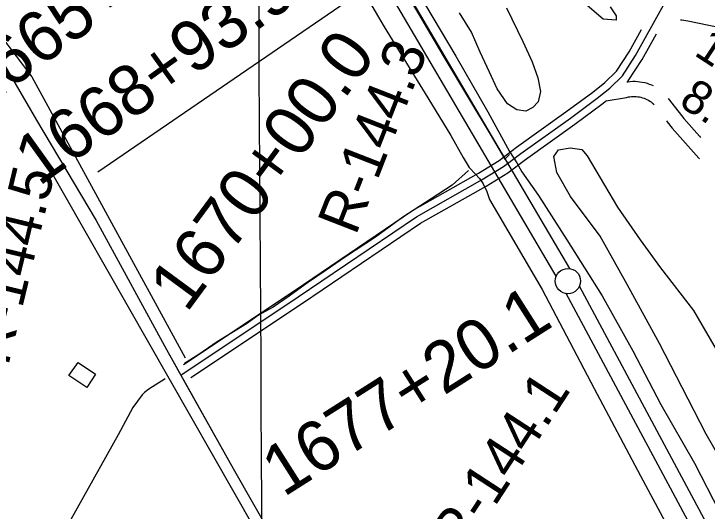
# Model space of a CAD drawing. Extents: x 3477039 to 3515015, y 546746 to 572297.
# Drawn here: x 3496548 to 3497919, y 561275 to 562259 of the extents above; entities that cross this region are included whole.
import ezdxf

# ---------------------------------------------------------------- set-up
doc = ezdxf.new("R2010")
doc.units = 0
for name, color, linetype in [('V-BLDG-OTLN', 7, 'Continuous'), ('V-FLOD-BASE', 7, 'Continuous'), ('V-GRID-MAJR', 7, 'Continuous'), ('V-LEVE-TOET', 7, 'Continuous'), ('V-RIVR-RANG', 7, 'Continuous'), ('V-RIVR-RANG-IDEN', 7, 'Continuous'), ('V-ROAD-CNTR', 7, 'Continuous'), ('V-SITE-VEGE', 7, 'Continuous'), ('V-SURV-IDEN', 7, 'Continuous'), ('V-SURV-LINE', 7, 'Continuous'), ('V-TOPO-MINR', 7, 'Continuous'), ('V-TOPO-SHOR', 7, 'Continuous')]:
    doc.layers.add(name, color=color, linetype=linetype)

msp = doc.modelspace()

# ---------------------------------------------------------------- linework, layer by layer
at = {"layer": 'V-BLDG-OTLN'}
msp.add_lwpolyline([(3496674.8850000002, 561568.976), (3496709.6350000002, 561545.756), (3496692.19, 561519.65), (3496656.9220000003, 561543.214)], close=True, dxfattribs=at)
at = {"layer": 'V-FLOD-BASE'}
msp.add_lwpolyline([(3496072.208, 562978.024), (3496198.731, 562942.932), (3496343.41, 562904.79), (3496508.679, 562860.148), (3496656.299, 562821.006), (3496768.595, 562788.941), (3496803.407, 562777.941), (3496844.078, 562761.012), (3496913.6240000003, 562725.748), (3496965.506, 562693.531), (3496995.821, 562668.801), (3497043.197, 562621.384), (3497108.16, 562557.169), (3497182.41, 562484.549), (3497238.077, 562426.77), (3497262.943, 562394.213), (3497296.559, 562345.399), (3497348.136, 562259.156), (3497396.784, 562175.876), (3497451.286, 562085.197), (3497489.725, 562020.638), (3497518.917, 561971.357), (3497528.301, 561980.636)], dxfattribs=at)
at = {"layer": 'V-GRID-MAJR'}
msp.add_spline([(3497073.037565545, 555496.0515890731), (3497056.56, 558259.177), (3497020.416, 564320.132), (3496984.272, 570381.104), (3496984.251, 570384.554)], degree=3, dxfattribs=at)
at = {"layer": 'V-LEVE-TOET'}
for points in [[(3495687.304, 563022.464), (3495831.693, 563028.606), (3495926.179, 563028.921), (3495972.9590000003, 563024.707), (3496046.356, 563009.4), (3496195.292, 562971.336), (3496374.8000000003, 562924.779), (3496582.252, 562869.745), (3496703.219, 562835.785), (3496803.19, 562802.384), (3496872.115, 562770.48), (3496947.965, 562726.2880000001), (3497018.085, 562674.257), (3497080.299, 562617.46), (3497178.154, 562521.957), (3497242.06, 562455.09), (3497293.311, 562393.546), (3497347.444, 562301.365), (3497421.936, 562175.383), (3497485.5840000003, 562065.21), (3497528.424, 561986.657)], [(3495981.995, 562925.794), (3496080.275, 562901.591), (3496182.9020000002, 562873.425), (3496314.361, 562838.527), (3496447.563, 562802.304), (3496648.447, 562746.437), (3496704.343, 562730.358), (3496741.877, 562716.136), (3496840.474, 562671.81), (3496902.377, 562636.011), (3496942.8880000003, 562607.777), (3496974.216, 562579.594), (3497053.376, 562503.013), (3497129.074, 562433.013), (3497160.832, 562403.956), (3497181.703, 562382.835), (3497212.9990000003, 562348.9670000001), (3497226.856, 562325.263), (3497280.116, 562233.525), (3497366.765, 562092.598), (3497411.8170000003, 562017.9670000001), (3497436.4930000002, 561974.955), (3497448.6210000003, 561954.76)], [(3497528.424, 561986.657), (3497542.917, 561964.223), (3497552.629, 561946.51), (3497585.2290000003, 561899.234), (3497641.639, 561811.598), (3497711.165, 561700.834), (3497772.363, 561592.079), (3497827.688, 561485.811), (3497893.75, 561369.671), (3497943.733, 561273.243), (3498006.863, 561159.081), (3498067.06, 561046.898), (3498120.455, 560946.525), (3498182.6040000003, 560832.37), (3498252.992, 560700.507), (3498311.216, 560586.372), (3498370.911, 560472.231), (3498438.395, 560347.252), (3498517.561, 560206.02), (3498570.0100000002, 560112.031), (3498655.586, 559976.65), (3498726.035, 559855.578), (3498788.259, 559755.156)], [(3497448.6210000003, 561954.76), (3497460.813, 561941.937), (3497468.612, 561933.063), (3497476.1550000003, 561922.84), (3497483.427, 561907.5920000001), (3497488.9280000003, 561891.532)], [(3497488.9280000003, 561891.532), (3497592.856, 561713.321), (3497695.362, 561517.182), (3497787.512, 561344.726), (3497870.5810000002, 561189.823), (3497886.562, 561155.61), (3497922.856, 561079.719), (3497970.409, 560984.5160000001), (3498039.598, 560849.8150000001), (3498106.674, 560727.375), (3498169.001, 560615.462), (3498239.082, 560483.38), (3498302.2090000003, 560359.212), (3498381.41, 560215.705), (3498491.829, 560026.082), (3498597.078, 559849.612), (3498655.131, 559754.784)]]:
    msp.add_lwpolyline(points, dxfattribs=at)
at = {"layer": 'V-ROAD-CNTR'}
for points in [[(3494343.6332746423, 562821.786330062), (3494659.220643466, 562837.669298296), (3494960.815040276, 562850.5892724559), (3495266.6884285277, 562866.1032414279), (3495500.762960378, 562876.4572207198), (3495620.742720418, 562881.016211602), (3495682.122597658, 562878.7272161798), (3495733.307495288, 562869.4842346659), (3495784.929392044, 562855.149263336), (3495836.687288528, 562830.8483119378), (3495887.869186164, 562796.0653815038), (3495994.9209720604, 562699.1955752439), (3496169.52062286, 562546.5178806), (3496324.772312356, 562410.131153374), (3496416.298129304, 562312.184349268), (3496470.894020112, 562245.1824832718), (3496524.223913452, 562166.701640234), (3496592.42477705, 562048.896875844), (3496710.395541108, 561850.2872730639), (3496849.4982629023, 561594.8367839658), (3496884.9791919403, 561531.6549103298)], [(3495784.929392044, 562855.149263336), (3495836.687288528, 562830.8483119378), (3495887.869186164, 562796.0653815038), (3495994.9209720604, 562699.1955752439), (3496169.52062286, 562546.5178806), (3496324.772312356, 562410.131153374), (3496416.298129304, 562312.184349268), (3496470.894020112, 562245.1824832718), (3496524.223913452, 562166.701640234), (3496592.42477705, 562048.896875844), (3496710.395541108, 561850.2872730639), (3496849.4982629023, 561594.8367839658), (3496981.761998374, 561359.3132550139), (3497177.7296064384, 561015.543942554), (3497344.6122726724, 560720.2865330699), (3497526.0809097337, 560393.234187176), (3497906.739148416, 559720.832531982)], [(3496878.1762055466, 561543.768886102), (3497110.424741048, 561698.6355763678), (3497343.9712739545, 561857.336258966), (3497474.2200134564, 561930.8751118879), (3497516.53792882, 561956.562060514), (3497550.804860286, 561982.9160078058), (3497648.600664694, 562052.7898680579), (3497701.835558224, 562092.0257895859), (3497726.6265086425, 562111.6957502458), (3497751.4764589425, 562136.2327011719), (3497777.678406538, 562176.387620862), (3497832.995295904, 562276.022421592), (3497884.8031922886, 562359.22825518)], [(3496883.3261952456, 561565.231843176), (3497102.0487578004, 561711.0795514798), (3497336.0552897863, 561870.092233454), (3497466.639028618, 561943.8200859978), (3497508.0479458, 561968.9560357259), (3497541.869878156, 561994.9669837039), (3497639.790682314, 562064.9298437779), (3497692.7215764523, 562103.941765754), (3497716.666528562, 562122.940727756), (3497739.7934823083, 562145.7766820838), (3497764.823432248, 562184.1366053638), (3497789.3669844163, 562228.3434349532)], [(3497760.574311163, 562124.1361859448), (3497763.159435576, 562126.6887202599), (3497790.533380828, 562168.63863636), (3497818.900169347, 562219.7320392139)], [(3497760.283941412, 562124.4119700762), (3497762.291918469, 562124.7442363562), (3497767.040576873, 562125.2673119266), (3497771.8155590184, 562125.5327898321), (3497776.604219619, 562125.5352052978), (3497781.381302, 562125.2757779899), (3497786.133468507, 562124.7571405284), (3497790.8565981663, 562123.9796110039), (3497795.5209432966, 562122.9449656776), (3497800.1260789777, 562121.6610731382), (3497804.659393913, 562120.1238035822), (3497809.0955959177, 562118.3437714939), (3497812.207878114, 562116.893278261)], [(3496898.058165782, 561538.9978956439), (3497118.8007242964, 561686.1916012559), (3497351.887258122, 561844.5802844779), (3497481.800998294, 561917.9301377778), (3497525.02791184, 561944.1680853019), (3497559.739842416, 561970.8650319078), (3497657.4106470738, 562040.6498923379), (3497710.949539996, 562080.1098134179), (3497720.2170067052, 562087.4628399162)], [(3497719.1962976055, 562086.9399962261), (3497759.420658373, 562093.642016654), (3497763.282509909, 562094.5002058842), (3497766.386081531, 562095.0137636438), (3497769.5174231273, 562095.3586880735), (3497772.656440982, 562095.5332101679), (3497775.7977803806, 562095.5347947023), (3497778.938698, 562095.3642220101), (3497782.0665314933, 562095.0228594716), (3497785.167401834, 562094.5123889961), (3497788.2390567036, 562093.8310343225), (3497791.2739210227, 562092.9849268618), (3497794.2486060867, 562091.9761964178), (3497797.1644040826, 562090.8062285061), (3497800.0162601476, 562089.4771080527), (3497802.790702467, 562087.9946543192), (3497805.477296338, 562086.3652628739), (3497808.0736816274, 562084.5874932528), (3497810.5688580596, 562082.6748421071), (3497812.0295716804, 562081.4209294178), (3497813.836680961, 562079.0218691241)], [(3497842.167319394, 562091.2727604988), (3497844.377342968, 562088.3388041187), (3497853.8455311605, 562076.1159288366), (3497863.4795151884, 562064.0243461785), (3497873.2782379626, 562052.0609614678), (3497883.2356365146, 562040.233095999), (3497893.3516790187, 562028.5419116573), (3497903.628676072, 562016.9896667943), (3497906.028302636, 562014.3636132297)], [(3497838.3521285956, 562047.4187242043), (3497840.142484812, 562045.1716538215), (3497850.197762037, 562032.8950385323), (3497860.4163634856, 562020.756904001), (3497870.8003209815, 562008.7560883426), (3497881.347323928, 561996.9003332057), (3497892.049819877, 561985.1879575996), (3497902.9148884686, 561973.6188123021), (3497904.2447929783, 561972.2408566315)], [(3496884.9791919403, 561531.6549103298), (3496981.761998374, 561359.3132550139), (3497177.7296064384, 561015.543942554), (3497344.6122726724, 560720.2865330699), (3497526.0809097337, 560393.234187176), (3497906.739148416, 559720.832531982), (3498102.6447566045, 559404.3021650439), (3498398.9351640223, 558897.4921786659), (3498714.302533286, 558355.897261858), (3498913.399135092, 558032.1899092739), (3499011.1859395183, 557897.511178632), (3499269.5474227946, 557543.9508857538), (3499385.340191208, 557402.6591683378), (3499670.8446201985, 557083.6958062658), (3499981.2859993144, 556735.7635021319), (3500083.10779567, 556622.88472789), (3500127.46270696, 556569.357834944), (3500201.255559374, 556502.8429679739), (3500336.9632879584, 556381.5222106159), (3500543.129875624, 556217.396538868), (3500745.793470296, 556030.2749131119)]]:
    msp.add_lwpolyline(points, dxfattribs=at)
at = {"layer": 'V-SITE-VEGE'}
for points in [[(3497727.248, 562272.828), (3497738.903, 562255.134), (3497738.8540000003, 562246.317), (3497713.399, 562248.42), (3497653.9390000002, 562299.686)], [(3497522.532, 562271.041), (3497554.4760000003, 562204.257), (3497572.861, 562163.998), (3497584.4390000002, 562132.59), (3497589.182, 562105.136), (3497585.147, 562084.591), (3497574.313, 562073.878), (3497560.557, 562066.12), (3497542.9420000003, 562069.157), (3497524.401, 562081.015), (3497503.9990000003, 562110.514), (3497488.514, 562143.903), (3497470.125, 562183.181), (3497452.715, 562222.462), (3497429.423, 562260.79)], [(3497977.2490000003, 561322.857), (3497917.009, 561427.1950000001), (3497869.455, 561519.685), (3497824.812, 561606.272), (3497760.718, 561723.383), (3497707.294, 561818.848), (3497648.873, 561897.6630000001), (3497621.667, 561944.911), (3497615.957, 561976.337), (3497624.864, 561990.022), (3497648.43, 561993.813), (3497670.9790000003, 561990.743), (3497681.7, 561977.931), (3497741.9560000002, 561876.536), (3497786.722, 561811.535), (3497826.637, 561756.368), (3497891.895, 561671.628), (3497941.452, 561586.976)]]:
    msp.add_lwpolyline(points, dxfattribs=at)
at = {"layer": 'V-SURV-LINE'}
for points in [[(3497302.133959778, 562341.3218390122), (3497646.563880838, 561754.9311758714)], [(3497620.6985608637, 561739.7329770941), (3497276.2689325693, 562326.1231418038)], [(3497666.4135172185, 561719.5667040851), (3498473.85465832, 560212.5805583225)], [(3498447.4012755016, 560198.430682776), (3497639.9599622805, 561705.4171497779)]]:
    msp.add_lwpolyline(points, dxfattribs=at)
msp.add_circle((3497643.74678, 561730.1103299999), 25, dxfattribs=at)
at = {"layer": 'V-TOPO-MINR'}
msp.add_lwpolyline([(3498024.7100427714, 562214.5041622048), (3497880.8431733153, 562244.2909408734), (3497868.7110827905, 562246.2563097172), (3497866.1828061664, 562246.5175662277)], dxfattribs=at)
at = {"layer": 'V-TOPO-SHOR'}
for p, q in [((3496713.6784987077, 561946.4604050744), (3497240.9106766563, 562307.578335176)), ((3496605.343119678, 561975.3498394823), (3497342.0236970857, 560682.547649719))]:
    msp.add_line(p, q, dxfattribs=at)
for points in [[(3496352.560568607, 562415.9137142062), (3496489.785382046, 562257.0218249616), (3496583.676043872, 562134.2417287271), (3496887.015105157, 561578.1201163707)], [(3497447.102, 561948.831), (3497415.012, 561920.069), (3497373.279, 561892.851), (3497317.39, 561856.808), (3497262.964, 561817.044), (3497204.088, 561778.0480000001), (3497165.33, 561751.553), (3497128.806, 561726.531), (3497092.275, 561700.023), (3497060.97, 561678.681), (3497031.923, 561662.522), (3497008.068, 561645.59), (3496949.952, 561609.559), (3496913.43, 561584.537), (3496885.114, 561566.889)], [(3496847.077, 561536.677), (3496815.034, 561516.082), (3496806.088, 561509.455), (3496801.607, 561505.025), (3496782.898, 561479.898), (3496754.37, 561425.876), (3496635.821, 561213.527), (3496574.306, 561104.768), (3496506.75, 560978.9720000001), (3496476.757, 560928.671), (3496450.508, 560883.5430000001), (3496418.264, 560828.802), (3496380.761, 560763.698), (3496351.4590000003, 560704.484), (3496325.965, 560661.581), (3496316.227, 560646.79)]]:
    msp.add_lwpolyline(points, dxfattribs=at)

# ---------------------------------------------------------------- texts
at = {"layer": 'V-RIVR-RANG'}
for s, p in [('12.1', (3497890.852512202, 562178.6457894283)), ('8.6', (3497860.5172921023, 562078.9631774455))]:
    msp.add_text(s, height=67, rotation=326.75832571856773, dxfattribs=at).set_placement(p)
at = {"layer": 'V-RIVR-RANG-IDEN'}
for s, height, rotation, p in [('R-144.3', 82.99999799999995, 68.69058081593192, (3497223.921763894, 561818.3869258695)), ('R-144.5', 82.99999799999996, 76.45606214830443, (3496536.6574816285, 561560.4546694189)), ('R-144.1', 82.99999799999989, 56.9048385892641, (3497434.886, 561183.904))]:
    msp.add_text(s, height=height, rotation=rotation, dxfattribs=at).set_placement(p)
at = {"layer": 'V-SURV-IDEN'}
for s, height, rotation, p in [('1665+43.7', 100.00000000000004, 36.58823544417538, (3496479.6088524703, 562063.2364698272)), ('1668+93.9', 100.00000000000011, 35.6489073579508, (3496597.3719933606, 561916.2511490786)), ('1670+00.0', 100.00000000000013, 53.6305769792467, (3496889.630775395, 561665.4953417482)), ('1677+20.1', 99.99999999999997, 32.44259046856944, (3497081.1841105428, 561301.3333669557))]:
    msp.add_text(s, height=height, rotation=rotation, dxfattribs=at).set_placement(p)

doc.saveas('drawing.dxf')
